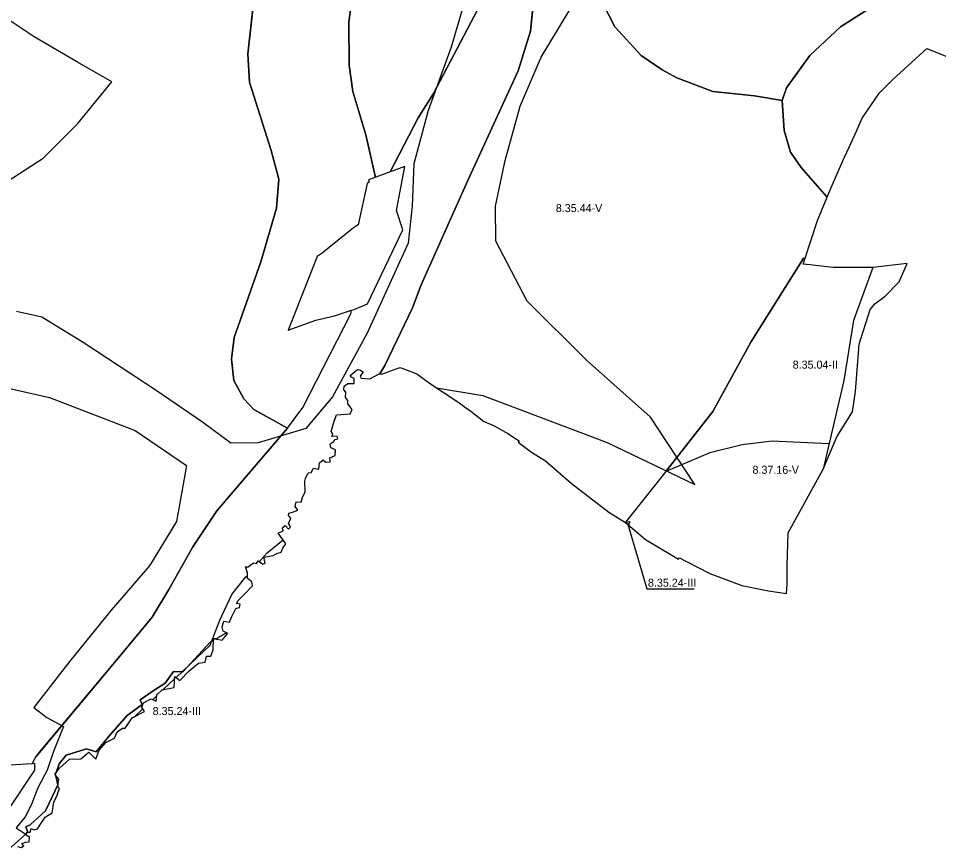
# Model space of a CAD drawing. Extents: x -547623 to -533936, y -1096714 to -1086523.
# Drawn here: x -541420 to -540270, y -1094274 to -1093236 of the extents above; entities that cross this region are included whole.
import ezdxf

# ---------------------------------------------------------------- set-up
doc = ezdxf.new("R2010")
doc.units = 0
for name, color, linetype in [('Vrstva 27', 7, 'Continuous'), ('Vrstva 28', 7, 'Continuous'), ('Vrstva 29', 7, 'Continuous')]:
    doc.layers.add(name, color=color, linetype=linetype)

msp = doc.modelspace()

# ---------------------------------------------------------------- linework, layer by layer
at = {"layer": 'Vrstva 27'}
msp.add_lwpolyline([(-540658.6, -1093866.4), (-540634.8, -1093948.4), (-540575.6, -1093948.4)], dxfattribs=at)
at = {"layer": 'Vrstva 28'}
for p, q in [((-541007, -1093240.5), (-541001.5, -1093200)), ((-541001.5, -1093200), (-541007, -1093240.5)), ((-541125, -1093209), (-541133, -1093280.5)), ((-541133, -1093280.5), (-541125, -1093209)), ((-540780, -1093252), (-540775.5, -1093207)), ((-540691, -1093215), (-540674.5, -1093246.5)), ((-540674.5, -1093246.5), (-540691, -1093215)), ((-540343.5, -1093215.5), (-540392.5, -1093246.5)), ((-540392.5, -1093246.5), (-540343.5, -1093215.5)), ((-540842, -1093217.5), (-540901, -1093330)), ((-541006.5, -1093294.5), (-541007, -1093240.5)), ((-541007, -1093240.5), (-541006.5, -1093294.5)), ((-540674.5, -1093246.5), (-540641.5, -1093282.5)), ((-540641.5, -1093282.5), (-540674.5, -1093246.5)), ((-540392.5, -1093246.5), (-540431, -1093282.5)), ((-540431, -1093282.5), (-540392.5, -1093246.5)), ((-540795.5, -1093301.5), (-540780, -1093252)), ((-541133, -1093280.5), (-541131, -1093316)), ((-541131, -1093316), (-541133, -1093280.5)), ((-540641.5, -1093282.5), (-540615.5, -1093300.5)), ((-540615.5, -1093300.5), (-540641.5, -1093282.5)), ((-540431, -1093282.5), (-540460, -1093323)), ((-540460, -1093323), (-540431, -1093282.5)), ((-541002, -1093327.5), (-541006.5, -1093294.5)), ((-541006.5, -1093294.5), (-541002, -1093327.5)), ((-540858.5, -1093439.5), (-540795.5, -1093301.5)), ((-540615.5, -1093300.5), (-540597, -1093310.5)), ((-540597, -1093310.5), (-540615.5, -1093300.5)), ((-541131, -1093316), (-541104, -1093401)), ((-541104, -1093401), (-541131, -1093316)), ((-540597, -1093310.5), (-540552, -1093327.5)), ((-540552, -1093327.5), (-540597, -1093310.5)), ((-540985.5, -1093381.5), (-541002, -1093327.5)), ((-541002, -1093327.5), (-540985.5, -1093381.5)), ((-540901, -1093330), (-540920.5, -1093360.5)), ((-540552, -1093327.5), (-540500, -1093333)), ((-540500, -1093333), (-540552, -1093327.5)), ((-540460, -1093323), (-540465.5, -1093338.5)), ((-540465.5, -1093338.5), (-540460, -1093323)), ((-540500, -1093333), (-540465.5, -1093338.5)), ((-540465.5, -1093338.5), (-540500, -1093333)), ((-540465.5, -1093338.5), (-540463, -1093376)), ((-540463, -1093376), (-540465.5, -1093338.5)), ((-540920.5, -1093360.5), (-540955.2, -1093427.6)), ((-540463, -1093376), (-540455, -1093403)), ((-540455, -1093403), (-540463, -1093376)), ((-540985.5, -1093381.5), (-540973.8, -1093434.8)), ((-540973.8, -1093434.7), (-540985.5, -1093381.5)), ((-541104, -1093401), (-541094.5, -1093437)), ((-541094.5, -1093437), (-541104, -1093401)), ((-540455, -1093403), (-540442, -1093422.5)), ((-540442, -1093422.5), (-540455, -1093403)), ((-540442, -1093422.5), (-540409.9, -1093458.9)), ((-540409.9, -1093458.9), (-540442, -1093422.5)), ((-541094.5, -1093437), (-541097.5, -1093473)), ((-541097.5, -1093473), (-541094.5, -1093437)), ((-540916.5, -1093569), (-540858.5, -1093439.5)), ((-540409.9, -1093458.9), (-540409.3, -1093459.5)), ((-540409.3, -1093459.5), (-540409.9, -1093458.9)), ((-541097.5, -1093473), (-541117, -1093540)), ((-541117, -1093540), (-541097.5, -1093473)), ((-540439.5, -1093536.3), (-540504.5, -1093640.5)), ((-540439, -1093535.5), (-540439.5, -1093536.3)), ((-540437.3, -1093536.1), (-540439, -1093535.5)), ((-541117, -1093540), (-541150, -1093634.5)), ((-541150, -1093634.5), (-541117, -1093540)), ((-540927.5, -1093597.5), (-540916.5, -1093569)), ((-540962, -1093669.5), (-540927.5, -1093597.5)), ((-541150, -1093634.5), (-541153.5, -1093661.5)), ((-541153.5, -1093661.5), (-541150, -1093634.5)), ((-540504.5, -1093640.5), (-540552, -1093727)), ((-541153.5, -1093661.5), (-541150.5, -1093688.5)), ((-541150.5, -1093688.5), (-541153.5, -1093661.5)), ((-540968.4, -1093679.9), (-540962, -1093669.5)), ((-541150.5, -1093688.5), (-541138, -1093711)), ((-541138, -1093711), (-541150.5, -1093688.5)), ((-541138, -1093711), (-541125.5, -1093724.5)), ((-541125.5, -1093724.5), (-541138, -1093711)), ((-541125.5, -1093724.5), (-541083.5, -1093748)), ((-541083.5, -1093748), (-541125.5, -1093724.5)), ((-540552, -1093727), (-540611, -1093802)), ((-541083.5, -1093748), (-541172, -1093851)), ((-540611, -1093802), (-540654.6, -1093856.9)), ((-541172, -1093851), (-541202, -1093896)), ((-540654.6, -1093856.9), (-540661, -1093864.9)), ((-540661.2, -1093865.7), (-540661.6, -1093865.5)), ((-540661.6, -1093865.5), (-540661.5, -1093865.5)), ((-540661.5, -1093865.5), (-540661.6, -1093865.5)), ((-540661, -1093864.9), (-540661.5, -1093865.5)), ((-540661.5, -1093865.5), (-540660.6, -1093865.3)), ((-540660.6, -1093865.3), (-540656, -1093864.5)), ((-540656, -1093864.5), (-540657.4, -1093868.9)), ((-541202, -1093896), (-541231.7, -1093949.2)), ((-541231.7, -1093949.2), (-541252.6, -1093983.6)), ((-541252.6, -1093983.6), (-541295.3, -1094034.9)), ((-541171.4, -1094010.2), (-541159.7, -1094003.5)), ((-541214.5, -1094052), (-541180, -1094015)), ((-541180, -1094015), (-541177.1, -1094013.4)), ((-541177.1, -1094013.4), (-541176, -1094012.7)), ((-541172.8, -1094010.9), (-541172, -1094010.5)), ((-541172, -1094010.5), (-541171.5, -1094010.2)), ((-541171.5, -1094010.2), (-541171.4, -1094010.2)), ((-541295.3, -1094034.9), (-541398, -1094158)), ((-541236.5, -1094066), (-541226, -1094051.5)), ((-541226, -1094051.5), (-541214.5, -1094052)), ((-541250, -1094075.1), (-541236.5, -1094066)), ((-541267.5, -1094087), (-541250, -1094075.1)), ((-541265, -1094093), (-541267.5, -1094087)), ((-541284, -1094106.5), (-541265, -1094093)), ((-541305.5, -1094131), (-541284, -1094106.5)), ((-541322.5, -1094152), (-541305.5, -1094131)), ((-541369, -1094167), (-541360, -1094156)), ((-541360, -1094156), (-541334.5, -1094148)), ((-541334.5, -1094148), (-541322.5, -1094152)), ((-541372.6, -1094177.9), (-541369, -1094167)), ((-541373.1, -1094182.1), (-541373.4, -1094181.1)), ((-541370.5, -1094193), (-541373.1, -1094182.1)), ((-541381.4, -1094215.9), (-541370.5, -1094193)), ((-541386, -1094225.5), (-541381.4, -1094215.9)), ((-541405, -1094243), (-541386, -1094225.5)), ((-541410.5, -1094245.5), (-541405, -1094243)), ((-541408.1, -1094252.3), (-541410.5, -1094245.5))]:
    msp.add_line(p, q, dxfattribs=at)
for points in [[(-540955.3, -1093427.9), (-540920.5, -1093360.5), (-540901, -1093330), (-540842, -1093217.5), (-540838.5, -1093190.5), (-540849, -1093101), (-540861.7, -1093000), (-540862, -1092997.5), (-540868, -1092925.5), (-540879, -1092867), (-540900, -1092783), (-540904.5, -1092783.5), (-540906, -1092767.5), (-540923.5, -1092710), (-540931.5, -1092692.5), (-540957.9, -1092654.2)], [(-541395.3, -1094154.7), (-541295.3, -1094034.9), (-541252.6, -1093983.6), (-541231.7, -1093949.2), (-541202, -1093896), (-541172, -1093851), (-541083.5, -1093748), (-541125.5, -1093724.5), (-541138, -1093711), (-541150.5, -1093688.5), (-541153.5, -1093661.5), (-541150, -1093634.5), (-541117, -1093540), (-541097.5, -1093473), (-541094.5, -1093437), (-541104, -1093401), (-541131, -1093316), (-541133, -1093280.5), (-541125, -1093209)], [(-540775.5, -1093207), (-540780, -1093252), (-540795.5, -1093301.5), (-540858.5, -1093439.5), (-540916.5, -1093569), (-540927.5, -1093597.5), (-540962, -1093669.5), (-540968.4, -1093679.9)], [(-540691, -1093215), (-540674.5, -1093246.5), (-540641.5, -1093282.5), (-540615.5, -1093300.5), (-540597, -1093310.5), (-540552, -1093327.5)], [(-540552, -1093327.5), (-540500, -1093333), (-540465.5, -1093338.5), (-540460, -1093323), (-540431, -1093282.5), (-540392.5, -1093246.5), (-540343.5, -1093215.5)], [(-541420.7, -1094270), (-541416.5, -1094271.6), (-541413, -1094269.5), (-541415.6, -1094266.6), (-541411, -1094264.8), (-541406.5, -1094264.5), (-541406, -1094258.7), (-541410, -1094255.8), (-541409.1, -1094252.4), (-541404.9, -1094252.2), (-541404, -1094247.6), (-541400, -1094249.5), (-541396.1, -1094248), (-541391.4, -1094241.1), (-541386.2, -1094233.4), (-541377.4, -1094228.2), (-541375.6, -1094215), (-541371.4, -1094206), (-541368.4, -1094197.9), (-541370.5, -1094195.2), (-541369.3, -1094186.2), (-541374.2, -1094180), (-541368.6, -1094172.5), (-541356, -1094161.1), (-541341.8, -1094160.7), (-541331.8, -1094152.4), (-541323, -1094161), (-541318.8, -1094150), (-541310.6, -1094140.3), (-541299.5, -1094134.8), (-541296.5, -1094127), (-541289.9, -1094122.4), (-541286.2, -1094122.6), (-541277.5, -1094109.7), (-541262.4, -1094101.4), (-541265.7, -1094096), (-541263.3, -1094090.6), (-541253.9, -1094085.9), (-541247.5, -1094088.5), (-541246.9, -1094080.6), (-541240.1, -1094074.5), (-541225.3, -1094071.7), (-541224.5, -1094058), (-541218, -1094062.7), (-541206.6, -1094050.8), (-541194.7, -1094041.4), (-541186.4, -1094039.9), (-541184.9, -1094032.7), (-541179.3, -1094032.7), (-541176.3, -1094024.6), (-541176, -1094010.3), (-541165.3, -1094012.5), (-541161.1, -1094007.6), (-541158.3, -1094004.3), (-541163.8, -1094001.3), (-541165, -1093996.4), (-541163.1, -1093988.8), (-541156.2, -1093990.1), (-541153.1, -1093983), (-541148.1, -1093972.9), (-541143.4, -1093971.9), (-541142.6, -1093967.7), (-541147.1, -1093966.6), (-541145, -1093963.1), (-541138.5, -1093956.2), (-541127.1, -1093944.5), (-541128.2, -1093939.8), (-541133.6, -1093935.4), (-541133.7, -1093928.4), (-541135.8, -1093921.9), (-541136.2, -1093920.9), (-541132.7, -1093920.8), (-541126.1, -1093916), (-541122.4, -1093916.6), (-541120.1, -1093913.4), (-541114.2, -1093917.7), (-541111.4, -1093916.3), (-541113.2, -1093909), (-541101.6, -1093907), (-541096.9, -1093904.4), (-541091.3, -1093902.8), (-541089.5, -1093897.6), (-541085.6, -1093892.1), (-541095.1, -1093879), (-541088.8, -1093876.2), (-541089.8, -1093872.3), (-541086.3, -1093869.2), (-541082.5, -1093874.1), (-541079.8, -1093871.6), (-541082.1, -1093867), (-541079.5, -1093860), (-541082.1, -1093856.7), (-541081.9, -1093853.9), (-541076.1, -1093852.4), (-541070.5, -1093850), (-541074.1, -1093845.5), (-541072.8, -1093839.7), (-541066.4, -1093840.3), (-541064.8, -1093834.5), (-541061.3, -1093827.1), (-541062.1, -1093813.8), (-541061.2, -1093810.6), (-541057.9, -1093803.5), (-541053.8, -1093803.2), (-541051.2, -1093797.9), (-541044.4, -1093798.8), (-541043.5, -1093791.1), (-541039, -1093787.2), (-541035.6, -1093790.4), (-541030.3, -1093790), (-541030.6, -1093784.9), (-541023.8, -1093782), (-541023.4, -1093774.7), (-541029.3, -1093772.3), (-541030.1, -1093767.5), (-541026.3, -1093765.5), (-541024, -1093761.9), (-541020.8, -1093761.1), (-541021.5, -1093757.6), (-541028.1, -1093758.2), (-541027, -1093755.2), (-541028.8, -1093752.1), (-541025.3, -1093739.1), (-541023.7, -1093734.8), (-541022.3, -1093731.1), (-541005.1, -1093729.9), (-541002.7, -1093724.6), (-541008.3, -1093717.5), (-541008.1, -1093713.3), (-541011.2, -1093709.6), (-541010.5, -1093702.9), (-541013.3, -1093700), (-541012.8, -1093695.4), (-541008.3, -1093692.1), (-541000.3, -1093692), (-541000.1, -1093685.6), (-541003.7, -1093684.2), (-541005.3, -1093682.2), (-540996.3, -1093674.6), (-540993.1, -1093674.9), (-540989.1, -1093677.5), (-540992.6, -1093682.7), (-540991.5, -1093685.3), (-540980.8, -1093686.2), (-540969.1, -1093679.8), (-540965.7, -1093680.5), (-540952.4, -1093675.5), (-540942.7, -1093672.1), (-540922.1, -1093679.9), (-540905.1, -1093692.3), (-540870.9, -1093715), (-540861.1, -1093721.8), (-540854.3, -1093726.5), (-540838.7, -1093739.1), (-540825.3, -1093744.7), (-540808.3, -1093754.5), (-540806.2, -1093755.9), (-540799.5, -1093760.4), (-540794.2, -1093763.8), (-540795.4, -1093765.5), (-540778.8, -1093777.9), (-540761.2, -1093788.5), (-540729.2, -1093816.3), (-540682, -1093852.8), (-540661.2, -1093865.7), (-540636.2, -1093886.9), (-540603.2, -1093906.5), (-540594.9, -1093911.4), (-540594, -1093909.9), (-540585.9, -1093914), (-540556.1, -1093929.1), (-540516.1, -1093944.2), (-540482.6, -1093950.8), (-540460.1, -1093954.3), (-540459.5, -1093942.5), (-540459.2, -1093919.1), (-540457.9, -1093878.5), (-540414.5, -1093798.9), (-540397.4, -1093758.6), (-540377.8, -1093727.3), (-540373.8, -1093702.1), (-540369.4, -1093643.1), (-540355.7, -1093599.6), (-540349.9, -1093592.5), (-540336.8, -1093582.9), (-540319.4, -1093565), (-540309.5, -1093542.1), (-540352.2, -1093547.3), (-540401.8, -1093547.2), (-540434.6, -1093543.4), (-540435.5, -1093543.3), (-540439.5, -1093542.9), (-540421.3, -1093488.5), (-540404.3, -1093447.4), (-540388.2, -1093410.4), (-540381.6, -1093396.2), (-540372.8, -1093377), (-540365.7, -1093360.7), (-540343.8, -1093329.3), (-540327.3, -1093312.6), (-540284.8, -1093273.6), (-540283.9, -1093274), (-540217.1, -1093300.8)], [(-541003.5, -1093600.6), (-541000.1, -1093599.5), (-540983.5, -1093592.6), (-540939.6, -1093500), (-540947.2, -1093476.2), (-540936.9, -1093421.1), (-540982.2, -1093437.9), (-540981.5, -1093440.8), (-540984.2, -1093442.2), (-540995.3, -1093493.8), (-541000.9, -1093497.5), (-541040.2, -1093529.3), (-541046.4, -1093533.4), (-541082.9, -1093625.4), (-541048.2, -1093613.1), (-541024.7, -1093607.4), (-541003.5, -1093600.6), (-541003.5, -1093600.6)], [(-540406.9, -1093767.2), (-540478, -1093764), (-540515.5, -1093768.5), (-540556, -1093778.5), (-540611, -1093802), (-540552, -1093727), (-540504.5, -1093640.5), (-540439.5, -1093536.3), (-540439, -1093535.5), (-540437.3, -1093536.1)], [(-540376.5, -1093613.4), (-540388.3, -1093688.5), (-540414.5, -1093798.9), (-540397.4, -1093758.6), (-540377.8, -1093727.3), (-540373.8, -1093702.1), (-540369.4, -1093643.1), (-540355.7, -1093599.6), (-540349.9, -1093592.5), (-540336.8, -1093582.9), (-540319.4, -1093565), (-540309.5, -1093542.1), (-540352.2, -1093547.3), (-540376.5, -1093613.4)], [(-541402.5, -1094167), (-541398, -1094158), (-541295.3, -1094034.9), (-541252.6, -1093983.6), (-541231.7, -1093949.2), (-541202, -1093896), (-541172, -1093851), (-541083.5, -1093748), (-541064.5, -1093722), (-541004.5, -1093605), (-541003.5, -1093600.5)], [(-541159.7, -1094003.5), (-541171.4, -1094010.2), (-541171.5, -1094010.2), (-541172, -1094010.5), (-541172.8, -1094010.9)], [(-541176, -1094012.7), (-541177.1, -1094013.4), (-541180, -1094015), (-541214.5, -1094052), (-541226, -1094051.5), (-541236.5, -1094066), (-541250, -1094075.1), (-541267.5, -1094087), (-541265, -1094093), (-541284, -1094106.5), (-541305.5, -1094131), (-541322.5, -1094152), (-541334.5, -1094148), (-541360, -1094156), (-541369, -1094167), (-541372.6, -1094177.9)], [(-541176, -1094010.3), (-541176, -1094012.7)], [(-541172.8, -1094010.9), (-541176, -1094010.3)], [(-541461.7, -1094268.2), (-541399.2, -1094174.8), (-541399.1, -1094166.6), (-541402.4, -1094166.8), (-541437.4, -1094168.9)], [(-541373.4, -1094181.1), (-541373.1, -1094182.1), (-541370.5, -1094193), (-541381.4, -1094215.9), (-541386, -1094225.5), (-541405, -1094243), (-541410.5, -1094245.5), (-541408.1, -1094252.3)], [(-541372.6, -1094177.9), (-541374.2, -1094180)], [(-541374.2, -1094180), (-541373.4, -1094181), (-541373.4, -1094181.1)], [(-541373.4, -1094181.1), (-541373.4, -1094181.1)], [(-541409.5, -1094253.8), (-541432, -1094274), (-541462.1, -1094268.1)], [(-541409.1, -1094252.4), (-541409.5, -1094253.8)], [(-541408.1, -1094252.3), (-541409.1, -1094252.4)]]:
    msp.add_lwpolyline(points, dxfattribs=at)
at = {"layer": 'Vrstva 29'}
for points in [[(-540851.5, -1093178.1), (-540878.9, -1093272.2), (-540907.8, -1093351), (-540925.8, -1093417.7), (-540928, -1093470.4), (-540932.8, -1093516.8), (-540984.2, -1093629.2), (-541027.2, -1093708.8), (-541060.7, -1093748.2), (-541120, -1093766), (-541154.3, -1093766.6), (-541189.6, -1093740.3), (-541247.5, -1093700.7), (-541339, -1093640.8), (-541390.3, -1093609.3), (-541422, -1093602)], [(-541286.5, -1094122.6), (-541285, -1094120.7), (-541277.5, -1094109.7), (-541274.6, -1094108.1), (-541264.3, -1094098.3), (-541265.7, -1094096), (-541263.3, -1094090.6), (-541253.9, -1094085.9), (-541252, -1094086.7), (-541247, -1094082), (-541246.9, -1094080.6), (-541240.1, -1094074.5), (-541238.8, -1094074.3), (-541224.7, -1094061), (-541224.5, -1094058), (-541222.8, -1094059.2), (-541180.1, -1094018.9), (-541168.2, -1093987.7), (-541152.9, -1093955.3), (-541135.5, -1093933.6), (-541133.6, -1093931.6), (-541133.7, -1093928.4), (-541136.2, -1093920.9), (-541132.7, -1093920.8), (-541126.1, -1093916), (-541122.4, -1093916.6), (-541120.1, -1093913.4), (-541118.6, -1093914.5), (-541108.9, -1093903.5), (-541089.1, -1093887.3), (-541095.1, -1093879), (-541088.8, -1093876.2), (-541089.8, -1093872.3), (-541086.3, -1093869.2), (-541082.5, -1093874.1), (-541079.8, -1093871.6), (-541082.1, -1093867), (-541079.5, -1093860), (-541082.1, -1093856.7), (-541081.9, -1093853.9), (-541076.1, -1093852.4), (-541070.5, -1093850), (-541074.1, -1093845.5), (-541072.8, -1093839.7), (-541066.4, -1093840.3), (-541064.8, -1093834.5), (-541061.3, -1093827.1), (-541062.1, -1093813.8), (-541061.2, -1093810.6), (-541057.9, -1093803.5), (-541053.8, -1093803.2), (-541051.2, -1093797.9), (-541044.4, -1093798.8), (-541043.5, -1093791.1), (-541039, -1093787.2), (-541035.6, -1093790.4), (-541030.3, -1093790), (-541030.6, -1093784.9), (-541023.8, -1093782), (-541023.4, -1093774.7), (-541029.3, -1093772.3), (-541030.1, -1093767.5), (-541026.3, -1093765.5), (-541024, -1093761.9), (-541020.8, -1093761.1), (-541021.5, -1093757.6), (-541028.1, -1093758.2), (-541027, -1093755.2), (-541028.8, -1093752.1), (-541025.3, -1093739.1), (-541022.3, -1093731.1), (-541005.1, -1093729.9), (-541002.7, -1093724.6), (-541008.3, -1093717.5), (-541008.1, -1093713.3), (-541011.2, -1093709.6), (-541010.5, -1093702.9), (-541013.3, -1093700), (-541012.8, -1093695.4), (-541008.3, -1093692.1), (-541000.3, -1093692), (-541000.1, -1093685.6), (-541003.7, -1093684.2), (-541005.3, -1093682.2), (-540996.3, -1093674.6), (-540993.1, -1093674.9), (-540989.1, -1093677.5), (-540992.6, -1093682.7), (-540991.5, -1093685.3), (-540980.8, -1093686.2), (-540969.1, -1093679.8), (-540965.7, -1093680.5), (-540952.4, -1093675.5), (-540942.7, -1093672.1), (-540922.1, -1093679.9), (-540905.1, -1093692.3), (-540897.6, -1093697.3), (-540839.4, -1093707.2), (-540684.3, -1093765.6), (-540574.8, -1093818), (-540630.1, -1093733.9), (-540709.9, -1093663), (-540784, -1093589.1), (-540823.2, -1093514.4), (-540823.8, -1093470.8), (-540811.7, -1093413.4), (-540793, -1093345.6), (-540766.6, -1093284.4), (-540723.2, -1093212.6)], [(-541449.7, -1093449.7), (-541388.8, -1093410.5), (-541345.7, -1093367.3), (-541323.3, -1093340.5), (-541302.9, -1093315.4), (-541346.1, -1093290.9), (-541399.9, -1093259.2), (-541449.4, -1093226.7)], [(-541443.7, -1093695.2), (-541380.8, -1093709.5), (-541273.7, -1093750.8), (-541209.8, -1093794.4), (-541222.1, -1093864.3), (-541256, -1093919.5), (-541303.8, -1093975.2), (-541355.5, -1094038.7), (-541400.3, -1094096.6), (-541384.1, -1094108.9), (-541363.3, -1094120.3), (-541375.9, -1094151.4), (-541383.9, -1094174.7), (-541395.6, -1094196.8), (-541404, -1094218.4), (-541411.4, -1094233), (-541422.7, -1094246.9), (-541409.9, -1094255.3), (-541409.1, -1094252.4), (-541404.9, -1094252.2), (-541404, -1094247.6), (-541400, -1094249.5), (-541396.1, -1094248), (-541391.4, -1094241.1), (-541386.2, -1094233.4), (-541377.4, -1094228.2), (-541375.6, -1094215), (-541371.4, -1094206), (-541368.4, -1094197.9), (-541370.5, -1094195.2), (-541369.3, -1094186.2), (-541374.2, -1094180), (-541368.6, -1094172.5), (-541356, -1094161.1), (-541341.8, -1094160.7), (-541331.8, -1094152.4), (-541323, -1094161), (-541318.8, -1094150), (-541310.6, -1094140.3), (-541299.5, -1094134.8), (-541296.5, -1094127), (-541289.9, -1094122.4), (-541286.5, -1094122.6)]]:
    msp.add_lwpolyline(points, dxfattribs=at)

# ---------------------------------------------------------------- texts
at = {"layer": 'Vrstva 27'}
for s, p in [('8.35.44-V', (-540748.3, -1093478)), ('8.35.04-II', (-540452.4, -1093673.5)), ('8.37.16-V', (-540502.6, -1093804.8)), ('8.35.24-III', (-540633.2, -1093945.8)), ('8.35.24-III', (-541252, -1094106))]:
    msp.add_text(s, height=10, dxfattribs=at).set_placement(p)

doc.saveas('drawing.dxf')
